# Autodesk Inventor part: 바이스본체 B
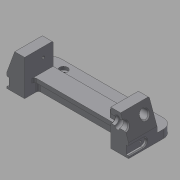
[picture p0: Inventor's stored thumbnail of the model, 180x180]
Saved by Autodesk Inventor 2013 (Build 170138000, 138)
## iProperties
Created: 2017-04
Part Number: 바이스본체 B
Material: 일반
Document SubType Name: Modeling
Designer: mduedu
Density: 1 g/cm^3
Author: mduedu
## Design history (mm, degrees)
sketch "스케치1"
  geometry: L1 (-75, 0)-(75, 0); L2 (-75, 0)-(-75, 17); L3 (-53, 17)-(53, 17); L4 (75, 17)-(75, 0); L5 (-75, 17)-(-65.173, 44); L6 (-65.173, 44)-(-53, 44); L7 (-53, 44)-(-53, 17); L8 (0, 0)-(0, 17); L9 (75, 17)-(65.173, 44); L10 (65.173, 44)-(53, 44); L11 (53, 44)-(53, 17); 1 further point
  constraints: 22 end point, 4 perpendicular, 2 horizontal alignment, 2 midpoint, 2 symmetric about line, 1 coincident, 1 collinear, 1 horizontal, 1 vertical
  dimensions: "d0" = 150 distance of L1.start L1.end; "d1" = 17 distance of L1.start L2.end; "d2" = 27 distance of L3.start L6.end; "d3" = 22 distance of L3.start L2.end; "d4" = 70 deg angle of L3 L5; "d54" = 20 deg angle of L9 L4
extrude "돌출1" new body sketch "스케치1" stored distance "d5" = 70; taper "d6" = 0 deg
sketch "스케치2"
  geometry: L1 (0, 70)-(106, 70) reference; L2 (106, 70)-(106, 0) reference; L3 (106, 0)-(0, 0) reference; L4 (0, 47)-(106, 47); L5 (106, 47)-(106, 23); L6 (106, 23)-(0, 23); L7 (0, 23)-(0, 47); L8 (0, 70)-(0, 0) reference; 2 further points
  constraints: 8 end point, 2 parallel, 2 point on line, 1 horizontal, 1 horizontal alignment, 1 midpoint, 1 perpendicular
  dimensions: "d7" = 24 distance between parallel lines of L6 L4
extrude "돌출2" cut sketch "스케치2" stored distance "d9" = 70; taper "d10" = 0 deg
sketch "스케치3"
  geometry: L1 (22, -23)-(128, -23) reference; L2 (128, -47)-(22, -47) reference; L3 (22, -18)-(128, -18); L4 (128, -52)-(22, -52); L5 (22, -18)-(22, -52); L6 (128, -18)-(128, -52); 1 further point
  constraints: 8 end point, 3 parallel, 2 point on line, 1 perpendicular
  dimensions: "d11" = 5 distance between parallel lines of L3 L1; "d12" = 5 distance between parallel lines of L4 L2
extrude "돌출3" cut sketch "스케치3" distance "d13" = 12; taper "d14" = 0 deg
fillet "모깎기1" dims "d15" = 3, "d16" = 3
sketch "스케치4"
  geometry: L1 (103, 23)-(3, 23) reference; L2 (0, 26)-(0, 0) reference; L3 (106, 0)-(0, 0) reference; L4 (106, 26)-(106, 0) reference; L5 (96, 0)-(90, 0); L6 (90, 0)-(90, 19.5); L7 (96, 19.5)-(96, 0); L8 (90, 19.5)-(96, 19.5); A1 r 3 centre (3, 26) between (0, 26) and (3, 23) reference; A2 r 3 centre (103, 26) between (103, 23) and (106, 26) reference; 1 further point
  constraints: 8 end point, 2 perpendicular, 1 horizontal, 1 parallel, 1 point on line
  dimensions: "d17" = 10 distance between parallel lines of L7 L4; "d18" = 6 distance between parallel lines of L7 L6; "d27" = 3.5 distance between parallel lines of L8 L1
extrude "돌출4" join sketch "스케치4" distance "d19" = 12; taper "d20" = 0 deg
chamfer "모따기1" distance "d21" = 3; stored, may be unused: second distance "d22" = 2, angle "d23" = 45 deg
chamfer "모따기2" distance "d24" = 3; stored, may be unused: second distance "d25" = 2, angle "d26" = 45 deg
sketch "스케치5"
  geometry: L1 (-15.5, 35.8)-(-15.5, -25.8) reference; L2 (19.5, 0)-(0, 0) reference; C1 r 6.5 at (9.5, 15); 1 further point
  constraints: 1 centre point
  dimensions: "d28" = 13 diameter of C1; "d30" = 15 distance from line of C1.centre L2; "d31" = 25 distance from line of C1.centre L1
extrude "돌출5" cut sketch "스케치5" stored distance "d32" = 12; taper "d33" = 0 deg
sketch "스케치6"
  geometry: C1 r 5 at (-10, 15); C2 r 5 at (-60, 15); A1 r 6.5 centre (-10, 15) between (-15.766, 12) and (-4.234, 12) reference; A2 r 6.5 centre (-60, 15) between (-65.766, 12) and (-54.234, 12) reference; 1 further point
  constraints: 2 centre point, 2 coincident
  dimensions: "d34" = 10 diameter of C1; "d35" = 10 diameter of C2 (= d34)
extrude "돌출6" cut sketch "스케치6" stored distance "d36" = 12; taper "d37" = 0 deg
chamfer "모따기3" distance "d38" = 1; stored, may be unused: second distance "d39" = 2, angle "d40" = 45 deg
chamfer "모따기4" distance "d41" = 1; stored, may be unused: second distance "d42" = 2, angle "d43" = 45 deg
sketch "스케치7"
  geometry: L1 (-35, 35.8)-(-35, -25.8) reference; L2 (-70, 0)-(0, 0) reference; C1 r 5 at (-35, 15); 1 further point
  constraints: 1 centre point, 1 point on line
  dimensions: "d44" = 10 diameter of C1; "d45" = 15 distance from line of C1.centre L2
extrude "돌출7" cut sketch "스케치7" stored distance "d46" = 12; taper "d47" = 0 deg
chamfer "모따기5" distance "d48" = 1; stored, may be unused: second distance "d49" = 2, angle "d50" = 45 deg
node "작업축1"
sketch "스케치8"
  geometry: L1 (-105, 32)-(105, 32) reference; L2 (58, 32)-(64, 32); L3 (64, 32)-(64, 40); L4 (64, 40)-(58, 40); L5 (58, 40)-(58, 32); L6 (53, 38)-(53, 26) reference; 1 further point
  constraints: 8 end point, 2 parallel, 1 horizontal, 1 perpendicular, 1 point on line
  dimensions: "d51" = 5 distance from line of L6 L2.start; "d52" = 6 distance of L3.end L4.end; "d53" = 16 diameter of L4 L1
revolve "회전1" sketch "스케치8" stored, may be unused: angle "d55" = 90 deg
fillet "모깎기2"
chamfer "모따기6" distance "d56" = 1; stored, may be unused: second distance "d57" = 2, angle "d58" = 45 deg
sketch "스케치9"
  geometry: L1 (17.5, 3)-(52.5, 3); L2 (52.5, 13)-(17.5, 13); L3 (70, 0)-(0, 0) reference; L4 (17.5, 8)-(52.5, 8); A1 r 5 centre (17.5, 8) between (17.5, 13) and (17.5, 3); A2 r 5 centre (52.5, 8) between (52.5, 3) and (52.5, 13); 3 further points
  constraints: 6 end point, 4 point on circle, 3 tangent, 2 centre point, 2 midpoint, 2 parallel, 1 horizontal, 1 vertical alignment
  dimensions: "d59" = 35 distance of L4.start L4.end; "d61" = 5 radius of A2; "d62" = 8 distance between parallel lines of L3 L4
extrude "돌출8" cut sketch "스케치9" distance "d63" = 3; taper "d64" = 0 deg
chamfer "모따기7" distance "d65" = 1; stored, may be unused: second distance "d66" = 2, angle "d67" = 45 deg
chamfer "모따기8" distance "d68" = 1; stored, may be unused: second distance "d69" = 2, angle "d70" = 45 deg
feature "분할1"
sketch "스케치10"
  geometry: A1 r 5 centre (0, 0) between (0, 5) and (0, -5) reference; 1 further point
  constraints: 1 coincident
hole "구멍1" sketch "스케치10" at (0, 0) diameter "d71" = 2.459; stored, may be unused: countersink angle "d75" = 90 deg, drill point angle "d77" = 120 deg; dims "d72" = 4.5, "d73" = 4, "d74" = 2, "d76" = 6
sketch "스케치11"
  geometry: L1 (0, 0)-(0, 27) reference; L2 (0, 27)-(-35, 27) reference; 2 further points
  dimensions: "d78" = 12 distance from line of point (-12, 15.5) L1; "d79" = 11.5 distance from line of point (-12, 15.5) L2
hole "구멍2" sketch "스케치11" at (-12, 15.5) diameter "d80" = 3.242; stored, may be unused: countersink angle "d84" = 90 deg, drill point angle "d86" = 120 deg; dims "d81" = 6, "d82" = 4, "d83" = 2, "d85" = 8
sketch "스케치12"
  geometry: L1 (-75, -35)-(-75, 0) reference; L2 (75, -35)-(75, 0) reference; L3 (75, -35)-(-75, -35); L4 (-75, -35)-(-75, -55); L5 (-75, -55)-(75, -55); L6 (75, -55)-(75, -35); 1 further point
  constraints: 8 end point, 2 parallel, 1 horizontal, 1 perpendicular, 1 point on line
  dimensions: "d87" = 20 distance of L3.end L4.end; "d89" = 150 distance of L4.end L5.end (derived)
extrude "돌출9" join sketch "스케치12" distance "d90" = 10; taper "d91" = 0 deg
sketch "스케치13"
  geometry: L1 (-75, 55)-(-75, 35) reference; L2 (75, 35)-(75, 55) reference; L3 (-75, 45)-(75, 45); 3 further points
  constraints: 2 end point, 2 midpoint, 2 point on line
  dimensions: "d92" = 50 horizontal distance of point (-50, 45) point (0, 0); "d93" = 100 distance of point (50, 45) point (-50, 45)
fillet "모깎기3" dims "d94" = 12
chamfer "모따기9" distance "d95" = 1; stored, may be unused: second distance "d96" = 2, angle "d97" = 45 deg
hole "구멍3" sketch "스케치13" diameter "d98" = 4.134; stored, may be unused: countersink angle "d102" = 90 deg, drill point angle "d104" = 118 deg; dims "d99" = 6, "d100" = 10, "d101" = 4, "d103" = 8
node "솔리드1"
mirror "대칭1"
mirror "대칭2"
mirror "대칭3"
mirror "대칭4"
node "투영된 루프1"
